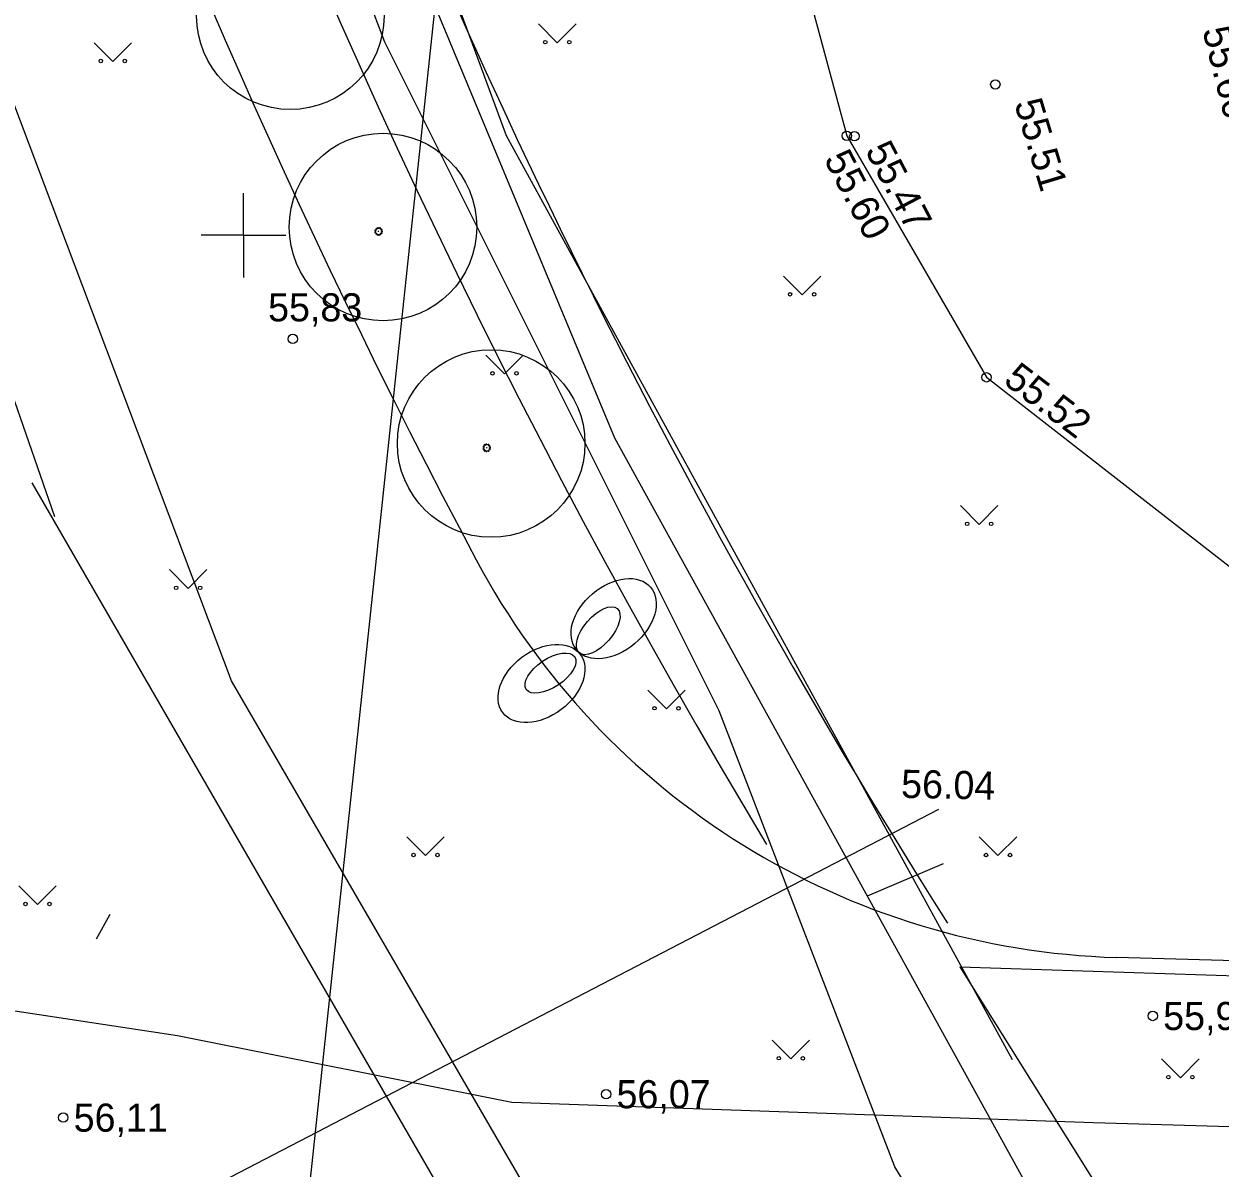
# Model space of a CAD drawing. Extents: x 9156 to 9809, y 2728 to 4000.
# Drawn here: x 9444.15 to 9476.03, y 3825.13 to 3855.63 of the extents above; entities that cross this region are included whole.
import ezdxf

# ---------------------------------------------------------------- set-up
doc = ezdxf.new("R2010")
doc.units = 0
for name, color, linetype in [('Level 12', 7, 'Continuous'), ('Level 14', 7, 'Continuous'), ('Level 15', 7, 'Continuous'), ('Level 16', 7, 'Continuous'), ('Level 17', 7, 'Continuous'), ('Level 18', 7, 'Continuous'), ('Level 41', 7, 'Continuous'), ('Level 54', 7, 'Continuous'), ('Level 56', 7, 'Continuous'), ('Level 59', 7, 'Continuous'), ('Level 61', 7, 'Continuous'), ('Level 7', 7, 'Continuous'), ('Level 8', 7, 'Continuous'), ('Level 9', 7, 'Continuous')]:
    doc.layers.add(name, color=color, linetype=linetype)

# ---------------------------------------------------------------- blocks, each defined once
blk = doc.blocks.new('MURU')
at = {"layer": 'Level 41'}
for p, q in [((-0.5, 0.5), (0, 0)), ((0, 0), (0.5, 0.5))]:
    blk.add_line(p, q, dxfattribs=at)
for centre in [(-0.32, 0.015), (0.32, 0.014)]:
    blk.add_circle(centre, 0.0466, dxfattribs=at)
blk = doc.blocks.new('KPUNKT')
at = {"layer": 'Level 59'}
blk.add_circle((0, 0), 0.125, dxfattribs=at)
blk = doc.blocks.new('KRTRIS')
at = {"layer": 'Level 61'}
for q in [(0, 1.125), (-1.125, 0), (1.125, 0), (0, -1.125)]:
    blk.add_line((0, 0), q, dxfattribs=at)

msp = doc.modelspace()

# ---------------------------------------------------------------- linework, layer by layer
at = {"layer": 'Level 12'}
msp.add_line((9436.81, 3818.227), (9468.538, 3834.695), dxfattribs=at)
at = {"layer": 'Level 14'}
for p, q in [((9444.967, 3842.49), (9431.28, 3881.958)), ((9466.679, 3804.785), (9444.363, 3843.396)), ((9446.434, 3831.886), (9446.071, 3831.23))]:
    msp.add_line(p, q, dxfattribs=at)
at = {"layer": 'Level 15'}
for p, q in [((9459.903, 3844.589), (9446.039, 3877.916)), ((9471.984, 3822.683), (9459.903, 3844.589)), ((9466.63, 3832.391), (9468.664, 3833.252))]:
    msp.add_line(p, q, dxfattribs=at)
at = {"layer": 'Level 16'}
for p, q in [((9449.679, 3838.123), (9432.161, 3884.564)), ((9468.103, 3806.398), (9449.679, 3838.123))]:
    msp.add_line(p, q, dxfattribs=at)
at = {"layer": 'Level 17'}
for p, q in [((9453.772, 3855.15), (9444.56, 3879.02)), ((9462.682, 3837.323), (9453.772, 3855.15)), ((9467.364, 3825.161), (9462.682, 3837.323)), ((9481.847, 3801.624), (9467.364, 3825.161))]:
    msp.add_line(p, q, dxfattribs=at)
for radius, start, end in [(192.9, 187.13653, 212.29226), (195.9, 187.89598, 211.0202)]:
    msp.add_arc((9631.829, 3934.713), radius, start, end, dxfattribs=at)
at = {"layer": 'Level 18'}
msp.add_line((9498, 3830.019), (9473.277, 3830.744), dxfattribs=at)
for centre, radius, start, end in [((9631.829, 3934.713), 198.9, 190.27283, 207.99609), ((9473.864, 3850.735), 20, 207.9961, 268.3202)]:
    msp.add_arc(centre, radius, start, end, dxfattribs=at)
at = {"layer": 'Level 54'}
msp.add_line((9458.429, 3887.462), (9450.115, 3809.187), dxfattribs=at)
for points in [[(9428.052, 3915.601), (9429.725, 3917.012), (9432.375, 3917.571), (9439.765, 3916.028), (9446.144, 3914.564), (9448.243, 3913.268), (9450.022, 3910.266), (9453.083, 3899.783), (9455.587, 3890.791), (9454.937, 3890.396), (9455.145, 3889.508), (9455.861, 3889.464), (9459.478, 3877.013), (9463.895, 3860.759), (9466.082, 3852.651)], [(9466.082, 3852.651), (9469.809, 3846.212), (9477.568, 3840.175)], [(9520.273, 3827.766), (9490.843, 3825.804), (9472.66, 3826.338), (9457.151, 3826.873), (9448.238, 3828.654), (9420.073, 3832.93)]]:
    msp.add_lwpolyline(points, dxfattribs=at)
for centre in [(9451.313, 3847.237), (9474.238, 3829.184), (9474.238, 3829.184), (9459.665, 3827.098), (9445.194, 3826.474)]:
    msp.add_circle(centre, 0.125, dxfattribs=at)
at = {"layer": 'Level 56'}
msp.add_line((9498, 3830.019), (9473.277, 3830.744), dxfattribs=at)
for centre, radius, start, end in [((9631.829, 3934.713), 192.9, 187.13653, 212.29226), ((9631.829, 3934.713), 195.9, 187.89598, 211.0202), ((9631.829, 3934.713), 198.9, 190.27283, 207.99609), ((9473.864, 3850.735), 20, 207.9961, 268.3202)]:
    msp.add_arc(centre, radius, start, end, dxfattribs=at)
at = {"layer": 'Level 7'}
for p, q in [((9446.918, 3879.882), (9457.002, 3852.664)), ((9457.002, 3852.664), (9470.487, 3828.02)), ((9469.095, 3830.492), (9520.66, 3828.82)), ((9469.095, 3830.492), (9514.803, 3757.492))]:
    msp.add_line(p, q, dxfattribs=at)
at = {"layer": 'Level 8'}
for centre, major_axis, ratio in [((9459.868, 3839.778), (-0.986, -0.837), 0.674652), ((9459.868, 3839.778), (-0.986, -0.837), 0.674652), ((9459.868, 3839.778), (-0.986, -0.837), 0.674652), ((9459.868, 3839.778), (-0.986, -0.837), 0.674652), ((9459.456, 3839.455), (-0.507, -0.589), 0.486914), ((9459.456, 3839.455), (-0.507, -0.589), 0.486914), ((9459.456, 3839.455), (-0.507, -0.589), 0.486914), ((9459.456, 3839.455), (-0.507, -0.589), 0.486914), ((9457.944, 3838.049), (1.034, 0.776), 0.674652), ((9457.944, 3838.049), (1.034, 0.776), 0.674652), ((9457.944, 3838.049), (1.034, 0.776), 0.674652), ((9457.944, 3838.049), (1.034, 0.776), 0.674652), ((9458.184, 3838.326), (0.646, 0.434), 0.486914), ((9458.184, 3838.326), (0.646, 0.434), 0.486914), ((9458.184, 3838.326), (0.646, 0.434), 0.486914), ((9458.184, 3838.326), (0.646, 0.434), 0.486914)]:
    msp.add_ellipse(centre, major_axis=major_axis, ratio=ratio, dxfattribs=at)
at = {"layer": 'Level 9'}
for p, q in [((9453.524, 3850.114), (9453.502, 3850.117)), ((9453.502, 3850.088), (9453.523, 3850.092)), ((9453.51, 3850.144), (9453.53, 3850.136)), ((9453.53, 3850.07), (9453.51, 3850.06)), ((9453.525, 3850.037), (9453.542, 3850.051)), ((9453.542, 3850.155), (9453.526, 3850.168)), ((9453.547, 3850.187), (9453.559, 3850.169)), ((9453.559, 3850.036), (9453.547, 3850.018)), ((9453.58, 3850.178), (9453.573, 3850.199)), ((9453.573, 3850.006), (9453.579, 3850.027)), ((9453.612, 3850.101), (9453.591, 3850.101)), ((9453.602, 3850.024), (9453.601, 3850.002)), ((9453.602, 3850.203), (9453.602, 3850.181)), ((9453.602, 3850.091), (9453.602, 3850.112)), ((9453.623, 3850.178), (9453.629, 3850.199)), ((9453.629, 3850.006), (9453.624, 3850.027)), ((9453.644, 3850.036), (9453.656, 3850.018)), ((9453.655, 3850.187), (9453.645, 3850.168)), ((9453.661, 3850.154), (9453.678, 3850.168)), ((9453.678, 3850.037), (9453.662, 3850.052)), ((9453.693, 3850.144), (9453.674, 3850.135)), ((9453.674, 3850.07), (9453.694, 3850.062)), ((9453.68, 3850.113), (9453.701, 3850.117)), ((9453.701, 3850.089), (9453.68, 3850.092)), ((9456.407, 3844.344), (9456.385, 3844.347)), ((9456.385, 3844.318), (9456.407, 3844.322)), ((9456.393, 3844.374), (9456.413, 3844.366)), ((9456.413, 3844.299), (9456.393, 3844.29)), ((9456.408, 3844.266), (9456.425, 3844.281)), ((9456.425, 3844.384), (9456.409, 3844.398)), ((9456.43, 3844.417), (9456.442, 3844.398)), ((9456.442, 3844.266), (9456.43, 3844.248)), ((9456.463, 3844.408), (9456.456, 3844.429)), ((9456.456, 3844.236), (9456.462, 3844.257)), ((9456.495, 3844.331), (9456.474, 3844.331)), ((9456.485, 3844.253), (9456.484, 3844.231)), ((9456.485, 3844.433), (9456.485, 3844.411)), ((9456.485, 3844.32), (9456.485, 3844.341)), ((9456.506, 3844.408), (9456.512, 3844.429)), ((9456.512, 3844.235), (9456.507, 3844.256)), ((9456.527, 3844.265), (9456.539, 3844.247)), ((9456.539, 3844.417), (9456.528, 3844.398)), ((9456.544, 3844.384), (9456.561, 3844.398)), ((9456.562, 3844.267), (9456.545, 3844.281)), ((9456.576, 3844.374), (9456.557, 3844.364)), ((9456.557, 3844.3), (9456.577, 3844.291)), ((9456.563, 3844.343), (9456.584, 3844.347)), ((9456.584, 3844.318), (9456.563, 3844.322))]:
    msp.add_line(p, q, dxfattribs=at)
for centre in [(9451.248, 3855.852), (9453.719, 3850.219), (9456.602, 3844.448)]:
    msp.add_circle(centre, 2.5, dxfattribs=at)
for centre, radius, start, end in [((9453.602, 3850.102), 0.101, 155.3123, 171.7042), ((9453.602, 3850.102), 0.101, 187.9671, 204.8625), ((9453.602, 3850.102), 0.0788, 171.5431, 187.6203), ((9453.602, 3850.102), 0.101, 220.7122, 237.1166), ((9453.602, 3850.102), 0.101, 122.8434, 139.0222), ((9453.602, 3850.102), 0.0788, 138.6432, 154.5795), ((9453.602, 3850.102), 0.0788, 204.4529, 220.4774), ((9453.602, 3850.102), 0.0788, 105.9559, 123.0564), ((9453.602, 3850.102), 0.0788, 237.451, 253.0843), ((9453.602, 3850.102), 0.101, 90.0356, 106.342), ((9453.602, 3850.102), 0.101, 253.2952, 269.5718), ((9453.602, 3850.102), 0.0788, 74.31, 90.043), ((9453.602, 3850.102), 0.0788, 269.9461, 286.3473), ((9453.602, 3850.102), 0.101, 57.6108, 74.1981), ((9453.602, 3850.102), 0.101, 285.972, 302.5562), ((9453.602, 3850.102), 0.0788, 302.254, 320.086), ((9453.602, 3850.102), 0.0788, 41.2062, 56.7795), ((9453.602, 3850.102), 0.0788, 8.0619, 24.0332), ((9453.602, 3850.102), 0.0788, 336.0557, 352.7558), ((9453.602, 3850.102), 0.101, 24.5394, 40.9852), ((9453.602, 3850.102), 0.101, 319.7777, 336.0738), ((9453.602, 3850.102), 0.101, 352.27, 8.583), ((9456.485, 3844.332), 0.101, 155.3123, 171.7042), ((9456.485, 3844.332), 0.101, 187.9671, 204.8625), ((9456.485, 3844.332), 0.0788, 171.5431, 187.6203), ((9456.485, 3844.332), 0.101, 220.7122, 237.1166), ((9456.485, 3844.332), 0.101, 122.8434, 139.0222), ((9456.485, 3844.332), 0.0788, 138.6432, 154.5795), ((9456.485, 3844.332), 0.0788, 204.4529, 220.4774), ((9456.485, 3844.332), 0.0788, 105.9559, 123.0564), ((9456.485, 3844.332), 0.0788, 237.451, 253.0843), ((9456.485, 3844.332), 0.101, 90.0356, 106.342), ((9456.485, 3844.332), 0.0788, 74.31, 90.043), ((9456.485, 3844.332), 0.0788, 269.9461, 286.3473), ((9456.485, 3844.332), 0.101, 57.6108, 74.1981), ((9456.485, 3844.332), 0.101, 285.972, 302.5562), ((9456.485, 3844.332), 0.0788, 302.254, 320.086), ((9456.485, 3844.332), 0.0788, 41.2062, 56.7795), ((9456.485, 3844.332), 0.0788, 8.0619, 24.0332), ((9456.485, 3844.332), 0.0788, 336.0557, 352.7558), ((9456.485, 3844.332), 0.101, 24.5394, 40.9852), ((9456.485, 3844.332), 0.101, 319.7777, 336.0738), ((9456.485, 3844.332), 0.101, 352.27, 8.583), ((9456.485, 3844.332), 0.101, 253.2952, 269.5718)]:
    msp.add_arc(centre, radius, start, end, dxfattribs=at)

# ---------------------------------------------------------------- block references
at = {"layer": 'Level 54'}
for name, p in [('MURU', (9458.365, 3855.134)), ('MURU', (9446.517, 3854.633)), ('KPUNKT', (9470.042, 3854.02)), ('KPUNKT', (9466.082, 3852.651)), ('KPUNKT', (9466.284, 3852.638)), ('KRTRIS', (9450, 3850)), ('MURU', (9464.891, 3848.411)), ('MURU', (9456.959, 3846.304)), ('KPUNKT', (9469.809, 3846.212)), ('MURU', (9469.61, 3842.291)), ('MURU', (9448.525, 3840.585)), ('MURU', (9461.276, 3837.374)), ('MURU', (9454.851, 3833.46)), ('MURU', (9470.112, 3833.46)), ('MURU', (9444.509, 3832.156)), ('MURU', (9464.59, 3828.042)), ('MURU', (9474.976, 3827.539))]:
    msp.add_blockref(name, p, dxfattribs=at)

# ---------------------------------------------------------------- texts
for s, rotation, p in [('55.60', 284.0279, (9475.558, 3855.472)), ('55.51', 286.7614, (9470.542, 3853.52)), ('55.60', 297.6082, (9465.461, 3852.028)), ('55.47', 297.6082, (9466.559, 3852.261)), ('55.52', 322.6335, (9470.226, 3846.066)), ('56.04', 358.7814, (9467.525, 3835.002))]:
    msp.add_text(s, height=0.75, rotation=rotation, dxfattribs=at).set_placement(p)
for s, p in [(' 55,83', (9450.377, 3847.703)), (' 55,92', (9474.238, 3828.809)), (' 56,07', (9459.665, 3826.723)), (' 56,11', (9445.194, 3826.099))]:
    msp.add_text(s, height=0.75, dxfattribs=at).set_placement(p)

doc.saveas('drawing.dxf')
